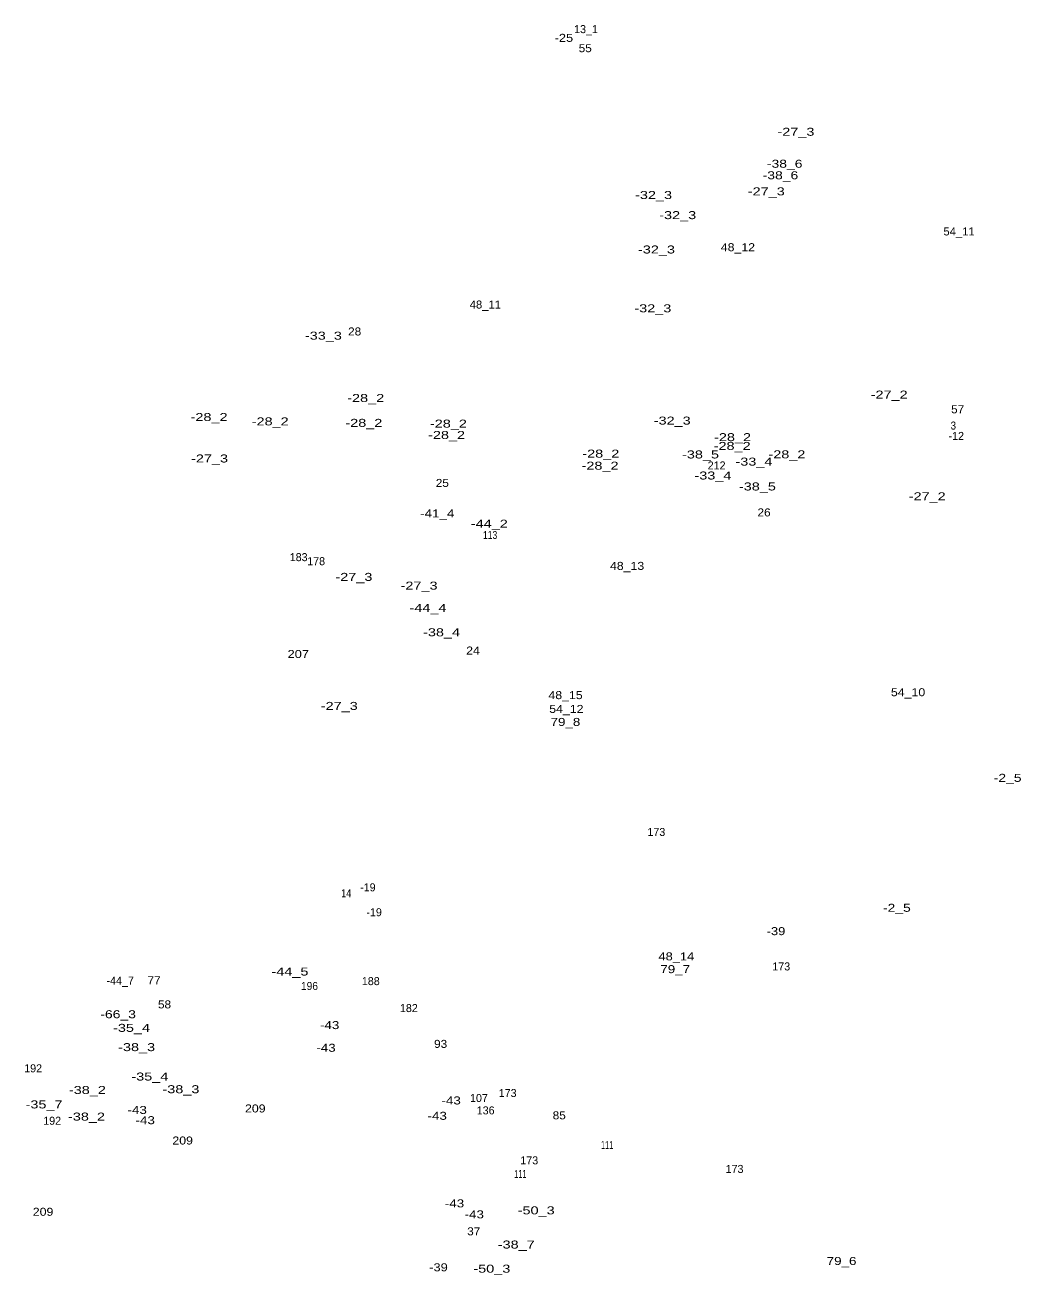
# Model space of a CAD drawing. Extents: x -660405 to -657848, y -988475 to -986360.
# Drawn here: x -658462 to -657964, y -987353 to -986728 of the extents above; entities that cross this region are included whole.
import ezdxf
from ezdxf.enums import TextEntityAlignment as Align

# ---------------------------------------------------------------- set-up
doc = ezdxf.new("R2010")
doc.units = 0
doc.header["$LTSCALE"] = 1.6
doc.layers.add('24', color=7, linetype='Continuous')

msp = doc.modelspace()

# ---------------------------------------------------------------- texts
at = {"layer": '24'}
for s, width, p in [('-25', 1.2, (-658192.67, -986736.24)), ('55', 1.1, (-658182, -986741.41)), ('-27_3', 1.35, (-658076.74, -986783.19)), ('-38_6', 1.3, (-658084.48, -986804.93)), ('-38_6', 1.3, (-658082.38, -986799.17)), ('-32_3', 1.35, (-658147.88, -986814.8)), ('-27_3', 1.35, (-658091.55, -986812.98)), ('-32_3', 1.35, (-658135.809, -986824.85)), ('54_11', 1.05, (-657995.27, -986833)), ('-32_3', 1.35, (-658146.419, -986842.03)), ('48_12', 1.15, (-658105.73, -986840.89)), ('48_11', 1.05, (-658231.9, -986869.54)), ('-32_3', 1.35, (-658148.24, -986871.43)), ('-33_3', 1.35, (-658312.819, -986885.1)), ('28', 1.1, (-658297.189, -986883)), ('-28_2', 1.35, (-658291.679, -986916.26)), ('-27_2', 1.35, (-658030.18, -986914.55)), ('57', 1.1, (-657995.96, -986921.89)), ('-28_2', 1.35, (-658369.919, -986925.77)), ('-28_2', 1.35, (-658339.39, -986927.96)), ('-28_2', 1.35, (-658292.59, -986928.69)), ('-28_2', 1.35, (-658250.36, -986929.06)), ('-32_3', 1.35, (-658138.559, -986927.55)), ('3', 0.9, (-657998.12, -986930.03)), ('-28_2', 1.35, (-658251.28, -986934.73)), ('-28_2', 1.35, (-658108.419, -986935.83)), ('-28_2', 1.35, (-658108.61, -986940.22)), ('-27_3', 1.35, (-658369.68, -986946.49)), ('-28_2', 1.35, (-658174.23, -986944.06)), ('-38_5', 1.35, (-658124.419, -986944.48)), ('-33_4', 1.35, (-658097.73, -986948.05)), ('-28_2', 1.35, (-658081.26, -986944.42)), ('-28_2', 1.35, (-658174.6, -986950.09)), ('-33_4', 1.35, (-658118.21, -986955)), ('25', 1.1, (-658253.4, -986958.71)), ('-38_5', 1.35, (-658095.99, -986960.48)), ('-27_2', 1.35, (-658011.17, -986965.38)), ('-41_4', 1.25, (-658255.93, -986973.96)), ('26', 1.1, (-658092.67, -986973.44)), ('-44_2', 1.35, (-658229.92, -986979.08)), ('113', 0.8, (-658229.53, -986984.73)), ('48_13', 1.15, (-658161.1, -987000.18)), ('-27_3', 1.35, (-658297.56, -987005.67)), ('-27_3', 1.35, (-658265.02, -987010.04)), ('-44_4', 1.35, (-658260.551, -987021.19)), ('-38_4', 1.35, (-658253.78, -987033.35)), ('24', 1.15, (-658238.059, -987042.49)), ('207', 1.2, (-658325.36, -987044.22)), ('48_15', 1.15, (-658191.84, -987064.77)), ('54_10', 1.15, (-658020.73, -987063.32)), ('-27_3', 1.35, (-658304.87, -987070.17)), ('54_12', 1.15, (-658191.429, -987071.67)), ('79_8', 1.25, (-658191.89, -987078.17)), ('-2_5', 1.3, (-657970.99, -987106.12)), ('14', 0.85, (-658301.39, -987163.78)), ('-2_5', 1.3, (-658026.34, -987171.08)), ('-39', 1.2, (-658086.71, -987182.75)), ('48_14', 1.2, (-658136.49, -987195.36)), ('-44_5', 1.35, (-658329.51, -987202.95)), ('79_7', 1.25, (-658137.061, -987201.74)), ('77', 1.1, (-658397.4, -987207.29)), ('196', 0.95, (-658319.76, -987210.16)), ('58', 1.1, (-658392.169, -987219.36)), ('-66_3', 1.3, (-658415.35, -987224.28)), ('-43', 1.25, (-658309.68, -987229.7)), ('-35_4', 1.35, (-658408.65, -987231.09)), ('-38_3', 1.35, (-658406.1, -987240.72)), ('-43', 1.25, (-658311.51, -987241.04)), ('93', 1.1, (-658254.24, -987239.09)), ('-35_4', 1.35, (-658399.51, -987255.41)), ('-38_2', 1.35, (-658430.709, -987262.13)), ('-38_3', 1.35, (-658383.98, -987261.75)), ('-43', 1.25, (-658248.99, -987267.37)), ('-35_7', 1.35, (-658452.35, -987269.35)), ('-43', 1.25, (-658405.83, -987272.12)), ('209', 1.15, (-658346.821, -987271.37)), ('-38_2', 1.35, (-658431.16, -987275.43)), ('-43', 1.25, (-658401.81, -987277.24)), ('-43', 1.25, (-658255.94, -987275.05)), ('85', 1.1, (-658194.99, -987274.82)), ('209', 1.15, (-658383.111, -987287.39)), ('111', 0.6, (-658171.07, -987289.64)), ('111', 0.6, (-658214.4, -987304.09)), ('209', 1.15, (-658452.841, -987323.01)), ('-43', 1.25, (-658247.31, -987318.82)), ('-50_3', 1.35, (-658206.52, -987322.31)), ('-43', 1.25, (-658237.44, -987324.31)), ('37', 1.1, (-658237.7, -987332.78)), ('-38_7', 1.35, (-658216.47, -987339.39)), ('79_6', 1.25, (-658053.95, -987347.61)), ('-39', 1.2, (-658255.31, -987350.78)), ('-50_3', 1.35, (-658228.66, -987351.46))]:
    msp.add_text(s, height=4, dxfattribs=dict(at, width=width)).set_placement(p, align=Align.CENTER)
for s, p in [('13_1', (-658181.62, -986731.88)), ('-12', (-657996.64, -986935.22)), ('212', (-658116.37, -986949.96)), ('183', (-658325.16, -986995.81)), ('178', (-658316.431, -986997.83)), ('173', (-658146.481, -987133.17)), ('-19', (-658290.59, -987160.85)), ('-19', (-658287.48, -987173.29)), ('173', (-658084.081, -987200.38)), ('-44_7', (-658414.306, -987207.45)), ('188', (-658289.13, -987207.73)), ('182', (-658270.11, -987221.19)), ('192', (-658457.811, -987251.31)), ('107', (-658235.091, -987266.14)), ('173', (-658220.76, -987263.66)), ('136', (-658231.75, -987272.34)), ('192', (-658448.311, -987277.52)), ('173', (-658209.971, -987297.31)), ('173', (-658107.41, -987301.6))]:
    msp.add_text(s, height=4, dxfattribs=at).set_placement(p, align=Align.CENTER)

doc.saveas('drawing.dxf')
